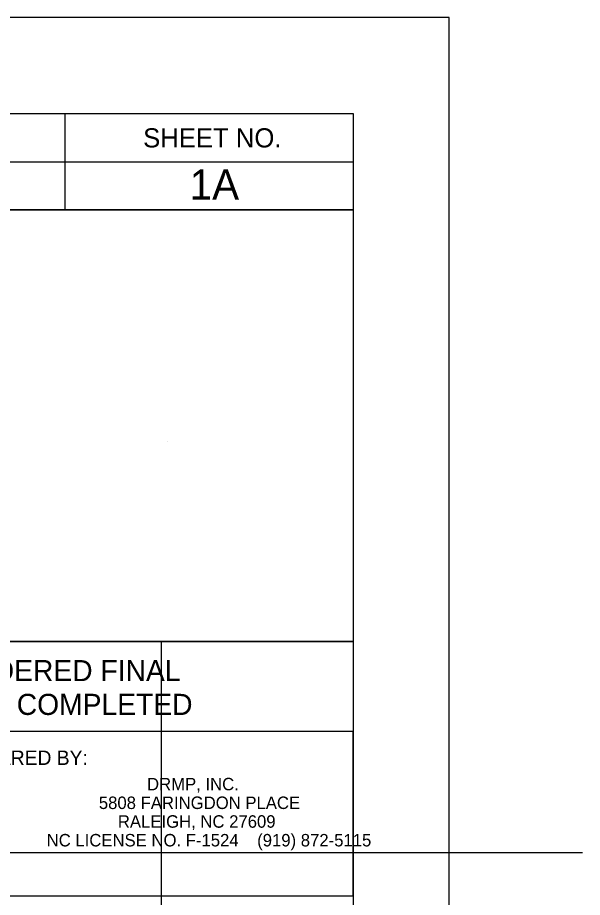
# Model space of a CAD drawing. Extents: x 573076.3 to 573113.7, y -55253.8 to -55199.3.
# Drawn here: x 573109.767 to 573112.708, y -55203.884 to -55199.298 of the extents above; entities that cross this region are included whole.
import ezdxf

# ---------------------------------------------------------------- set-up
doc = ezdxf.new("R2010")
doc.units = 0
for name, color, linetype in [('Pattern 2', 7, 'Continuous'), ('Pattern 3', 7, 'Continuous'), ('Prop DSN Text', 7, 'Continuous'), ('Scratch_Level_1', 7, 'Continuous'), ('Sheet Plan CELL', 7, 'Continuous'), ('Sheet Plot Border Inside CELL', 7, 'Continuous'), ('Sheet Sticker Exception Certification CELL', 7, 'Continuous')]:
    doc.layers.add(name, color=color, linetype=linetype)

msp = doc.modelspace()

# ---------------------------------------------------------------- linework, layer by layer
at = {"layer": 'Pattern 3'}
msp.add_lwpolyline([(573107.5132, -55203.8768), (573111.5139, -55203.8768), (573111.5139, -55203.0202), (573107.5132, -55203.0202)], close=True, dxfattribs=at)
at = {"layer": 'Scratch_Level_1'}
for p, q in [((573110.547, -55201.5095), (573110.547, -55201.5095)), ((573111.5139, -55202.5502), (573076.2547, -55202.5502)), ((573110.5142, -55202.5502), (573110.5142, -55220.7984)), ((573082.5142, -55203.6502), (573112.708, -55203.6502))]:
    msp.add_line(p, q, dxfattribs=at)
at = {"layer": 'Sheet Plan CELL'}
for p, q in [((573110.0144, -55200.2999), (573110.0144, -55199.7984)), ((573107.5132, -55200.0494), (573111.5142, -55200.0497))]:
    msp.add_line(p, q, dxfattribs=at)
for points in [[(573081.5142, -55199.7984), (573111.5142, -55199.7984), (573111.5142, -55220.7984), (573081.5142, -55220.7984)], [(573107.5132, -55199.7984), (573111.5142, -55199.7984), (573111.5142, -55200.3002), (573107.5132, -55200.3002)], [(573109.5142, -55200.3002), (573111.5142, -55200.3002), (573111.5142, -55202.5502), (573109.5142, -55202.5502)]]:
    msp.add_lwpolyline(points, close=True, dxfattribs=at)
at = {"layer": 'Sheet Plot Border Inside CELL'}
msp.add_lwpolyline([(573112.0142, -55199.2984), (573078.0142, -55199.2984), (573078.0142, -55221.2984), (573112.0142, -55221.2984)], close=True, dxfattribs=at)
at = {"layer": 'Sheet Sticker Exception Certification CELL'}
for p, q in [((573107.5132, -55202.5502), (573111.5139, -55202.5502)), ((573111.5139, -55202.5502), (573111.5139, -55203.0202)), ((573111.5139, -55203.0202), (573107.5132, -55203.0202))]:
    msp.add_line(p, q, dxfattribs=at)

# ---------------------------------------------------------------- texts
at = {"layer": 'Pattern 2'}
for s, height, p in [('PLANS PREPARED BY:', 0.074995, (573109.0345, -55203.1937)), ('DRMP, INC.', 0.065, (573110.4408, -55203.326)), ('5808 FARINGDON PLACE', 0.064996, (573110.1898, -55203.4235)), ('RALEIGH, NC 27609', 0.064996, (573110.2889, -55203.521)), ('NC LICENSE NO. F-1524    (919) 872-5115', 0.064996, (573109.918, -55203.6185))]:
    msp.add_text(s, height=height, rotation=360, dxfattribs=at).set_placement(p)
at = {"layer": 'Prop DSN Text'}
msp.add_text('1A', height=0.1575, rotation=0, dxfattribs=at).set_placement((573110.6627, -55200.2474))
at = {"layer": 'Sheet Plan CELL'}
msp.add_text('SHEET NO.', height=0.1, rotation=0, dxfattribs=at).set_placement((573110.4204, -55199.9752))
at = {"layer": 'Sheet Sticker Exception Certification CELL'}
for s, p in [('DOCUMENT NOT CONSIDERED FINAL', (573107.9346, -55202.7571)), ('UNLESS ALL SIGNATURES COMPLETED', (573107.8332, -55202.9331))]:
    msp.add_text(s, height=0.11, dxfattribs=at).set_placement(p)

doc.saveas('drawing.dxf')
